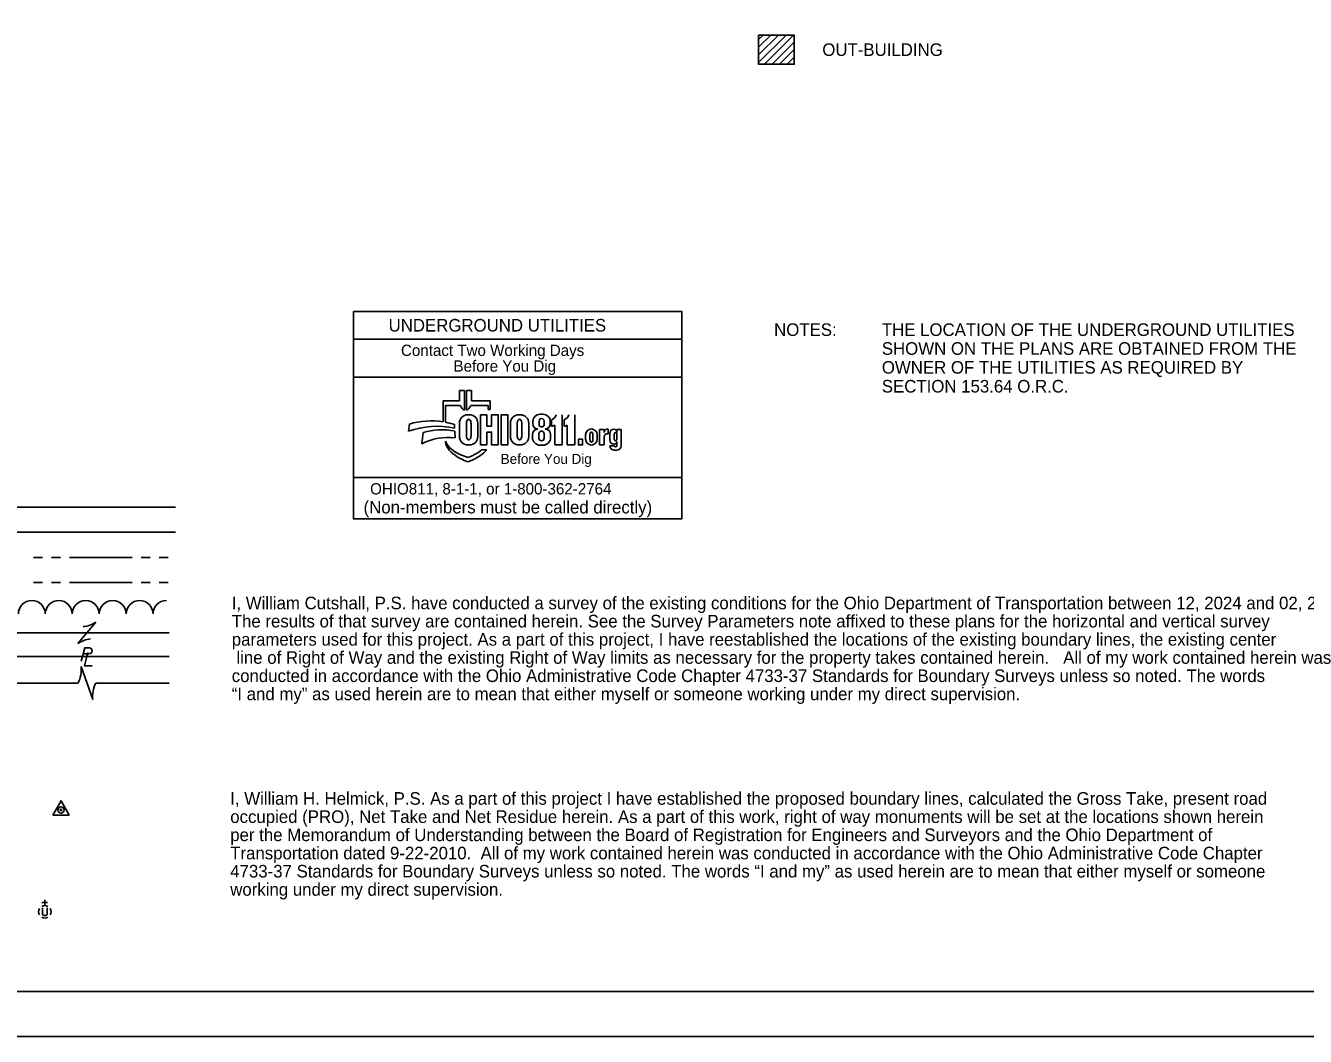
# Model space of a CAD drawing. Extents: x 0 to 34, y 0 to 22.
# Drawn here: x 12.45 to 26.71, y 0 to 11.25 of the extents above; entities that cross this region are included whole.
import ezdxf

# ---------------------------------------------------------------- set-up
doc = ezdxf.new("R2010")
doc.units = 0
for name, color, linetype in [('SH_Border', 7, 'Continuous'), ('SH_Cut_Line', 7, 'Continuous'), ('SH_Data', 7, 'Continuous'), ('SH_Text', 7, 'Continuous')]:
    doc.layers.add(name, color=color, linetype=linetype)

msp = doc.modelspace()

# ---------------------------------------------------------------- linework, layer by layer
at = {"layer": 'SH_Border'}
msp.add_lwpolyline([(1.5, 21.5), (33.5, 21.5), (33.5, 0.5), (1.5, 0.5)], close=True, dxfattribs=at)
at = {"layer": 'SH_Cut_Line'}
msp.add_lwpolyline([(0, 0), (34, 0), (34, 22), (0, 22)], close=True, dxfattribs=at)
at = {"layer": 'SH_Data'}
for p, q in [((17.345, 7.192), (17.288, 7.192)), ((17.288, 7.192), (17.288, 7.076)), ((17.345, 6.971), (17.345, 7.192)), ((17.422, 7.192), (17.366, 7.192)), ((17.366, 7.192), (17.366, 6.971)), ((17.422, 7.076), (17.422, 7.192)), ((17.288, 7.076), (17.104, 7.076)), ((17.104, 7.076), (17.104, 6.842)), ((17.131, 6.837), (17.131, 7.022)), ((17.131, 7.022), (17.299, 7.022)), ((17.411, 7.022), (17.606, 7.022)), ((17.631, 7.076), (17.422, 7.076)), ((17.606, 7.022), (17.606, 6.978)), ((17.631, 6.978), (17.631, 7.076)), ((17.398, 6.921), (17.381, 6.921)), ((17.593, 6.92), (17.522, 6.92)), ((17.522, 6.92), (17.522, 6.585)), ((17.606, 6.978), (17.631, 6.978)), ((17.966, 6.921), (17.948, 6.921)), ((18.104, 6.846), (18.104, 6.82)), ((18.174, 6.808), (18.174, 6.85)), ((18.219, 6.926), (18.184, 6.926)), ((18.23, 6.85), (18.23, 6.808)), ((18.298, 6.82), (18.298, 6.846)), ((18.314, 6.794), (18.314, 6.865)), ((18.431, 6.92), (18.431, 6.585)), ((18.454, 6.794), (18.454, 6.865)), ((18.571, 6.92), (18.571, 6.585)), ((16.73, 6.818), (16.72, 6.736)), ((16.884, 6.723), (16.869, 6.597)), ((17.233, 6.77), (17.233, 6.811)), ((17.24, 6.665), (17.234, 6.739)), ((17.287, 6.827), (17.287, 6.679)), ((17.364, 6.691), (17.364, 6.819)), ((17.416, 6.819), (17.416, 6.691)), ((17.492, 6.679), (17.492, 6.827)), ((17.593, 6.585), (17.593, 6.727)), ((17.855, 6.827), (17.855, 6.679)), ((17.931, 6.691), (17.931, 6.819)), ((17.983, 6.819), (17.983, 6.691)), ((18.059, 6.679), (18.059, 6.827)), ((18.101, 6.701), (18.101, 6.666)), ((18.171, 6.659), (18.171, 6.702)), ((18.231, 6.702), (18.231, 6.659)), ((18.303, 6.666), (18.303, 6.701)), ((18.348, 6.585), (18.348, 6.804)), ((18.488, 6.585), (18.488, 6.804)), ((18.899, 6.756), (18.848, 6.756)), ((18.848, 6.756), (18.848, 6.585)), ((18.899, 6.723), (18.899, 6.756)), ((18.934, 6.709), (18.942, 6.709)), ((18.942, 6.761), (18.938, 6.761)), ((18.942, 6.709), (18.942, 6.761)), ((18.962, 6.64), (18.962, 6.713)), ((19.012, 6.65), (19.012, 6.703)), ((19.042, 6.724), (19.042, 6.757)), ((19.042, 6.757), (19.088, 6.757)), ((19.042, 6.703), (19.042, 6.65)), ((19.088, 6.757), (19.088, 6.576)), ((17.13, 6.627), (17.133, 6.609)), ((17.381, 6.585), (17.398, 6.585)), ((17.522, 6.585), (17.593, 6.585)), ((17.948, 6.585), (17.966, 6.585)), ((18.185, 6.581), (18.218, 6.581)), ((18.431, 6.585), (18.348, 6.585)), ((18.571, 6.585), (18.488, 6.585)), ((18.693, 6.649), (18.693, 6.696)), ((18.74, 6.648), (18.74, 6.696)), ((18.774, 6.696), (18.774, 6.648)), ((18.821, 6.696), (18.821, 6.649)), ((18.848, 6.585), (18.899, 6.585)), ((18.899, 6.585), (18.899, 6.675)), ((18.962, 6.576), (19.012, 6.576)), ((19.042, 6.576), (19.042, 6.624)), ((17.386, 6.445), (17.323, 6.466)), ((17.379, 6.396), (17.446, 6.424)), ((17.429, 6.463), (17.386, 6.445)), ((17.591, 6.529), (17.531, 6.529)), ((17.589, 6.528), (17.591, 6.529)), ((19.039, 6.527), (19.011, 6.527)), ((17.34, 6.413), (17.379, 6.396)), ((19.764, 5.761), (16.106, 5.761))]:
    msp.add_line(p, q, dxfattribs=at)
for points in [[(16.106, 8.071), (19.764, 8.071), (19.764, 7.763), (16.106, 7.763)], [(16.106, 7.763), (19.764, 7.763), (19.764, 7.339), (16.106, 7.339)], [(16.106, 7.339), (19.764, 7.339), (19.764, 6.223), (16.106, 6.223)], [(18.612, 6.648), (18.658, 6.648), (18.658, 6.585), (18.612, 6.585)], [(16.106, 6.223), (19.764, 6.223), (19.764, 5.761), (16.106, 5.761)]]:
    msp.add_lwpolyline(points, close=True, dxfattribs=at)
for points in [[(17.593, 6.727), (17.646, 6.727), (17.646, 6.585), (17.717, 6.585), (17.717, 6.92), (17.646, 6.92), (17.646, 6.794), (17.593, 6.794), (17.593, 6.92)], [(17.753, 6.585), (17.825, 6.585), (17.825, 6.92), (17.753, 6.92), (17.753, 6.585)], [(18.161, 6.762), (18.161, 6.762)], [(18.242, 6.762), (18.242, 6.762)]]:
    msp.add_lwpolyline(points, dxfattribs=at)
for centre, radius, start, end in [((17.395, 7.06), 0.103, 201.9296, 240.7469), ((17.316, 7.06), 0.103, 299.2531, 338.0704), ((16.97, 5.996), 0.856, 81.0007, 106.3144), ((17.381, 6.827), 0.0936, 90, 180), ((17.398, 6.827), 0.0936, 0, 90), ((17.948, 6.827), 0.0936, 90, 180), ((17.966, 6.827), 0.0936, 0, 90), ((18.184, 6.846), 0.0798, 90, 180), ((18.219, 6.846), 0.0798, 0, 90), ((18.279, 6.95), 0.0925, 292.5572, 340.7355), ((18.419, 6.95), 0.0925, 292.5572, 340.7355), ((17.036, 5.859), 0.933, 77.8238, 109.8274), ((17.093, 5.987), 0.766, 79.44, 105.8467), ((16.97, 5.996), 0.856, 72.1402, 79.2074), ((18.161, 6.701), 0.0605, 90, 180), ((18.163, 6.82), 0.0586, 180, 268.1442), ((18.24, 6.82), 0.0586, 272.2058, 0), ((18.242, 6.701), 0.0605, 0, 90), ((18.306, 6.886), 0.0925, 275.1733, 297.0931), ((18.446, 6.886), 0.0925, 275.1733, 297.0931), ((18.76, 6.696), 0.0669, 92.5886, 180), ((18.754, 6.696), 0.0669, 0, 87.4114), ((18.938, 6.723), 0.0384, 90, 180), ((18.934, 6.675), 0.0345, 90, 180), ((19.01, 6.713), 0.048, 92.6865, 180), ((19.005, 6.724), 0.0367, 0, 86.9262), ((17.169, 6.004), 0.665, 83.8248, 116.8021), ((17.326, 6.703), 0.21, 201.0457, 232.5314), ((17.281, 6.634), 0.15, 189.6817, 216.0884), ((17.381, 6.679), 0.0936, 180, 270), ((17.398, 6.679), 0.0936, 270, 0), ((17.948, 6.679), 0.0936, 180, 270), ((17.966, 6.679), 0.0936, 270, 0), ((18.185, 6.666), 0.0847, 180, 270), ((18.218, 6.666), 0.0847, 270, 0), ((18.76, 6.649), 0.0669, 180, 267.4114), ((18.754, 6.649), 0.0669, 272.5886, 0), ((19.01, 6.64), 0.0484, 180, 265.7132), ((19.011, 6.576), 0.0489, 180, 270), ((19.009, 6.624), 0.0327, 264.7825, 0), ((19.039, 6.576), 0.0489, 270, 0), ((17.421, 6.736), 0.323, 216.0884, 235.7167), ((17.527, 6.966), 0.541, 232.5314, 241.794), ((17.595, 6.991), 0.632, 235.7167, 246.2325), ((17.438, 6.799), 0.352, 241.794, 250.9821), ((17.279, 6.809), 0.377, 293.4582, 312.0712), ((17.279, 6.809), 0.419, 293.4582, 317.8286)]:
    msp.add_arc(centre, radius, start, end, dxfattribs=at)
for centre, major_axis, ratio, start_param, end_param in [((17.39, 6.819), (0, 0.0506), 0.514403, 4.712389, 7.853982), ((17.957, 6.819), (0, 0.0506), 0.514403, 4.712389, 7.853982), ((18.202, 6.85), (0.0283, 0), 0.969373, 0, 3.141593), ((18.201, 6.702), (0, 0.0374), 0.794529, 4.712389, 7.853982), ((18.202, 6.808), (0.0283, 0), 0.818453, 3.141593, 6.283185), ((18.757, 6.696), (0, 0.0304), 0.553236, 4.712389, 7.853982), ((19.027, 6.703), (0, 0.0192), 0.777179, 4.712389, 7.853982), ((17.39, 6.691), (0, 0.0506), 0.514403, 1.570796, 4.712389), ((17.957, 6.691), (0, 0.0506), 0.514403, 1.570796, 4.712389), ((18.201, 6.659), (0.0297, 0), 0.959837, 3.141593, 6.283185), ((18.757, 6.648), (0, 0.0322), 0.522014, 1.570796, 4.712389), ((19.027, 6.65), (0, 0.0192), 0.777179, 1.570796, 4.712389), ((19.027, 6.576), (0.015, 0), 0.959012, 3.141593, 6.283185)]:
    msp.add_ellipse(centre, major_axis=major_axis, ratio=ratio, start_param=start_param, end_param=end_param, dxfattribs=at)
at = {"layer": 'SH_Text'}
for p, q in [((20.62, 11.147), (20.621, 11.148)), ((20.62, 11.097), (20.672, 11.148)), ((20.62, 11.012), (20.756, 11.148)), ((20.62, 10.927), (20.841, 11.148)), ((20.62, 10.842), (20.926, 11.148)), ((20.685, 10.822), (21.01, 11.148)), ((20.769, 10.822), (21.017, 11.07)), ((20.854, 10.822), (21.017, 10.985)), ((20.939, 10.822), (21.017, 10.901)), ((20.62, 10.827), (20.625, 10.822)), ((10.643, 5.893), (14.126, 5.893)), ((10.643, 5.613), (14.126, 5.613)), ((12.542, 5.333), (12.642, 5.333)), ((12.742, 5.333), (12.842, 5.333)), ((12.942, 5.333), (13.642, 5.333)), ((13.742, 5.333), (13.842, 5.333)), ((13.942, 5.333), (14.042, 5.333)), ((12.542, 5.053), (12.642, 5.053)), ((12.742, 5.053), (12.842, 5.053)), ((12.942, 5.053), (13.642, 5.053)), ((13.742, 5.053), (13.842, 5.053)), ((13.942, 5.053), (14.042, 5.053)), ((13.038, 4.373), (13.238, 4.613)), ((12.272, 4.493), (14.055, 4.493)), ((13.138, 4.493), (13.138, 4.493)), ((12.272, 4.229), (14.055, 4.229)), ((13.095, 4.258), (13.16, 4.258)), ((13.135, 4.227), (13.135, 4.227)), ((13.073, 4.118), (13.203, 3.749)), ((12.272, 3.933), (13.038, 3.933)), ((13.138, 3.933), (13.138, 3.933)), ((13.238, 3.933), (14.055, 3.933)), ((12.7, 1.489), (12.637, 1.489)), ((12.641, 1.43), (12.641, 1.361)), ((12.669, 1.457), (12.669, 1.52)), ((12.696, 1.43), (12.696, 1.361)), ((12.669, 1.387), (12.669, 1.387))]:
    msp.add_line(p, q, dxfattribs=at)
for points in [[(20.62, 11.148), (21.017, 11.148), (21.017, 10.822), (20.62, 10.822)], [(12.759, 2.463), (12.939, 2.463), (12.849, 2.624)]]:
    msp.add_lwpolyline(points, close=True, dxfattribs=at)
for points in [[(13.074, 4.179), (13.113, 4.327), (13.165, 4.327)], [(13.149, 4.275), (13.109, 4.127), (13.197, 4.127)]]:
    msp.add_lwpolyline(points, dxfattribs=at)
for radius in [0.035, 0.008]:
    msp.add_circle((12.849, 2.521), radius, dxfattribs=at)
for centre, radius, start, end in [((12.524, 4.703), 0.15, 0.0098, 179.9926), ((12.824, 4.703), 0.15, 0.0098, 179.9926), ((13.124, 4.703), 0.15, 0.0098, 179.9926), ((13.424, 4.703), 0.15, 0.0098, 179.9926), ((13.724, 4.703), 0.15, 0.0098, 179.9926), ((14.024, 4.703), 0.15, 89.9955, 179.9926), ((13.08, 4.828), 0.267, 273.6945, 306.337), ((13.196, 4.158), 0.267, 93.6945, 126.337), ((13.16, 4.293), 0.0345, 270.471, 81.3281), ((12.741, 4.085), 0.334, 332.9422, 5.5848), ((13.535, 3.782), 0.334, 152.9422, 185.5848), ((12.669, 1.387), 0.07, 60.0184, 120.0157), ((12.669, 1.387), 0.07, 150.0184, 209.9816), ((12.669, 1.387), 0.07, 239.9843, 299.9816), ((12.669, 1.374), 0.03, 205.1924, 334.8076), ((12.669, 1.387), 0.07, 330.0184, 29.9816)]:
    msp.add_arc(centre, radius, start, end, dxfattribs=at)

# ---------------------------------------------------------------- texts
at = {"layer": 'SH_Data'}
for s, height, p in [('UNDERGROUND UTILITIES', 0.14, (16.498, 7.847)), ('Contact Two Working Days', 0.126, (16.636, 7.575)), ('Before You Dig', 0.126, (17.221, 7.4)), ('Before You Dig', 0.1118, (17.747, 6.373)), ('OHIO811, 8-1-1, or 1-800-362-2764', 0.126, (16.292, 6.033)), ('(Non-members must be called directly)', 0.14, (16.219, 5.822))]:
    msp.add_text(s, height=height, dxfattribs=at).set_placement(p)
at = {"layer": 'SH_Text'}
for s, p in [('OUT-BUILDING', (21.329, 10.915)), ('NOTES:', (20.792, 7.798)), ('THE LOCATION OF THE UNDERGROUND UTILITIES', (21.992, 7.798)), ('SHOWN ON THE PLANS ARE OBTAINED FROM THE', (21.992, 7.588)), ('OWNER OF THE UTILITIES AS REQUIRED BY', (21.992, 7.378)), ('SECTION 153.64 O.R.C.', (21.992, 7.168)), ('I, William Cutshall, P.S. have conducted a survey of the existing conditions for the Ohio Department of Transportation between 12, 2024 and 02, 2025.  ', (14.751, 4.755)), ('The results of that survey are contained herein. See the Survey Parameters note affixed to these plans for the horizontal and vertical survey ', (14.751, 4.553)), ('parameters used for this project. As a part of this project, I have reestablished the locations of the existing boundary lines, the existing center', (14.751, 4.35)), (' line of Right of Way and the existing Right of Way limits as necessary for the property takes contained herein.   All of my work contained herein was ', (14.751, 4.148)), ('conducted in accordance with the Ohio Administrative Code Chapter 4733-37 Standards for Boundary Surveys unless so noted. The words ', (14.751, 3.945)), ('“I and my” as used herein are to mean that either myself or someone working under my direct supervision.', (14.751, 3.743)), ('I, William H. Helmick, P.S. As a part of this project I have established the proposed boundary lines, calculated the Gross Take, present road ', (14.734, 2.579)), ('occupied (PRO), Net Take and Net Residue herein. As a part of this work, right of way monuments will be set at the locations shown herein ', (14.734, 2.376)), ('per the Memorandum of Understanding between the Board of Registration for Engineers and Surveyors and the Ohio Department of ', (14.734, 2.174)), ('Transportation dated 9-22-2010.  All of my work contained herein was conducted in accordance with the Ohio Administrative Code Chapter ', (14.734, 1.971)), ('4733-37 Standards for Boundary Surveys unless so noted. The words “I and my” as used herein are to mean that either myself or someone ', (14.734, 1.769)), ('working under my direct supervision.', (14.734, 1.566))]:
    msp.add_text(s, height=0.14, dxfattribs=at).set_placement(p)

doc.saveas('drawing.dxf')
